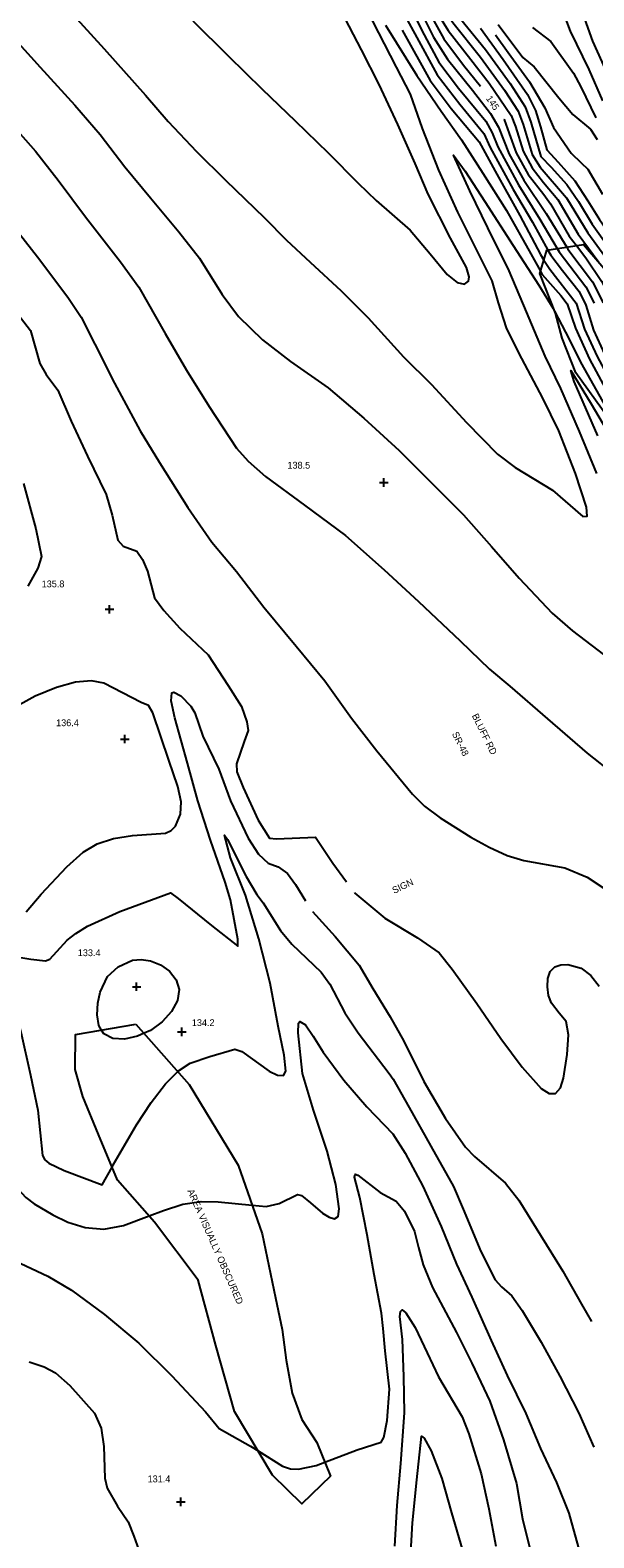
# Model space of a CAD drawing. Extents: x 1475150 to 2003689, y 770235 to 1112803.
# Drawn here: x 2002493.7 to 2002659.6, y 770837.9 to 771281.4 of the extents above; entities that cross this region are included whole.
import ezdxf

# ---------------------------------------------------------------- set-up
doc = ezdxf.new("R2010")
doc.units = 0
for name, color, linetype in [('RD_DTM_Major1', 7, 'Continuous'), ('RD_DTM_Major1_Lbl', 7, 'Continuous'), ('RD_DTM_Major2', 7, 'Continuous'), ('RD_DTM_Minor1', 7, 'Continuous'), ('RD_DTM_Minor2', 7, 'Continuous'), ('RD_DTM_Obscure', 7, 'Continuous'), ('RD_DTM_Spot_Elev', 7, 'Continuous'), ('RD_TX_Misc1', 7, 'Continuous')]:
    doc.layers.add(name, color=color, linetype=linetype)

msp = doc.modelspace()

# ---------------------------------------------------------------- linework, layer by layer
at = {"layer": 'RD_DTM_Major1'}
for points in [[(2002572.22, 771348.32), (2002573.98, 771345.49), (2002577.35, 771341.32), (2002584.21, 771333.66), (2002588.04, 771328.3), (2002594.85, 771316.81), (2002600.6, 771307.87), (2002604.96, 771301.61), (2002605.97, 771297.81), (2002610.02, 771288.75), (2002615.43, 771278.87), (2002621.3, 771271.13), (2002626.24, 771264.94)], [(2002505.43, 771287.05), (2002515.49, 771275.9), (2002527.71, 771262.34), (2002534.33, 771254.58), (2002542.66, 771245.73), (2002551.18, 771237.34), (2002562.67, 771226.24), (2002569.19, 771219.64), (2002576.1, 771213.22), (2002585.28, 771204.7), (2002593.19, 771196.77), (2002603.59, 771185.34), (2002611.84, 771177.15), (2002622.17, 771165.97), (2002631.32, 771156.68), (2002636.45, 771152.77), (2002647.44, 771146.13), (2002656.34, 771138.4), (2002657.65, 771138.48), (2002657.48, 771141.15), (2002654.26, 771151.06), (2002649.3, 771163.55), (2002644.63, 771173.15), (2002637.52, 771186.52), (2002633.96, 771193.89), (2002631.57, 771201.26), (2002629.69, 771207.66), (2002625.75, 771215.49), (2002619.56, 771227.86), (2002614.03, 771240.2), (2002609.17, 771252.46), (2002605.63, 771262.63), (2002601.57, 771270.55), (2002592.83, 771287.51)], [(2002598.29, 771282.91), (2002607.56, 771268.03), (2002614.7, 771257.57), (2002620.71, 771249.16), (2002627, 771239.37), (2002633.93, 771228.36), (2002641.08, 771215.63), (2002643.95, 771210.51)], [(2002630.69, 771280.05), (2002634.41, 771274.84), (2002640.69, 771266.18), (2002645.22, 771258.55), (2002647.73, 771252.77), (2002652.97, 771245.24), (2002655.86, 771242.37), (2002657.82, 771240.5), (2002662.21, 771233.14)], [(2002633.18, 771255.15), (2002633.23, 771255.09), (2002634.67, 771250.97), (2002636.76, 771245.36), (2002640.31, 771239), (2002644.89, 771233.03), (2002646.86, 771230.34), (2002652.4, 771220.85), (2002654.53, 771218.04)], [(2002491.78, 771148.03), (2002495.42, 771134.7), (2002497.04, 771126.58), (2002496.03, 771123.14), (2002493.09, 771117.87)], [(2002486.81, 771009.34), (2002493.88, 771008.19), (2002498.27, 771007.64), (2002499.54, 771008.14), (2002501.56, 771010.38), (2002504.63, 771013.75), (2002507.15, 771015.74), (2002510.62, 771017.88), (2002520.12, 771022.23), (2002535.04, 771027.72), (2002537.29, 771026.02), (2002547.09, 771018.1), (2002554.87, 771012), (2002554.88, 771014.09), (2002552.73, 771025.64), (2002551.09, 771030.78), (2002546.76, 771043.18), (2002543.12, 771054.78), (2002540.05, 771065.8), (2002536.34, 771079.12), (2002535.23, 771084.16), (2002535.4, 771086.53), (2002536.04, 771086.74), (2002538.07, 771085.6), (2002541.05, 771082.59), (2002542.18, 771080.66), (2002544.5, 771073.8), (2002549.22, 771064.09), (2002552.66, 771054.73), (2002557.89, 771043.77), (2002560.94, 771039.09), (2002563.77, 771036.36), (2002566.68, 771035.33), (2002569.47, 771033.4), (2002571.84, 771030.16), (2002574.72, 771025.34)], [(2002576.86, 771022.2), (2002583.53, 771014.84), (2002590.51, 771006.44), (2002594.56, 770999.56), (2002599.68, 770991.22), (2002603.74, 770984.01), (2002609.55, 770972.21), (2002615.96, 770961.34), (2002621.83, 770952.86), (2002624.5, 770950.16), (2002633.66, 770942.29), (2002637.54, 770937.31), (2002643.96, 770927), (2002650.46, 770916.36), (2002655.97, 770906.66), (2002658.93, 770901.54)], [(2002605.7, 770831.98), (2002606.26, 770842.36), (2002607.56, 770855.02), (2002608.89, 770867.88), (2002609.67, 770867.25), (2002611.71, 770863.59), (2002614.92, 770855.4), (2002617.72, 770845.32), (2002620.86, 770834.63)]]:
    msp.add_lwpolyline(points, dxfattribs=at)
at = {"layer": 'RD_DTM_Major2'}
for points in [[(2002654.53, 771218.04), (2002657.25, 771214.47), (2002661.88, 771207.57), (2002665.07, 771201.19), (2002668.33, 771190.58), (2002672.37, 771182.9), (2002679.57, 771170.99), (2002683.76, 771163.78), (2002685.58, 771159.2), (2002690.3, 771152.5), (2002695.01, 771145.03), (2002698.68, 771139.17), (2002704.48, 771129.17), (2002711.31, 771116.67), (2002715.88, 771105.6), (2002718.71, 771098.65), (2002724.7, 771088.03), (2002731.15, 771076.17), (2002737.25, 771064.57), (2002741.23, 771052.36), (2002742.65, 771048.71), (2002746.13, 771042.89), (2002752.29, 771034.5), (2002755.03, 771032.17)], [(2002643.95, 771210.51), (2002644.46, 771209.59), (2002649.94, 771203.39), (2002651.75, 771200.95), (2002654.18, 771193.76), (2002658.38, 771184.61), (2002665.58, 771171.25), (2002674.36, 771155.85), (2002675.88, 771153.09)]]:
    msp.add_lwpolyline(points, dxfattribs=at)
at = {"layer": 'RD_DTM_Minor1'}
for points in [[(2002563.7, 771348.73), (2002564.68, 771347.23), (2002571.43, 771336.99), (2002577.44, 771328.72), (2002582, 771323.14), (2002588.01, 771313.39), (2002593.54, 771304.04), (2002599.77, 771293.47), (2002607.5, 771279.21), (2002613.52, 771268.25), (2002620.16, 771259.63), (2002627.23, 771250.99), (2002629.12, 771246.88), (2002635.91, 771234.5), (2002641.58, 771224.89), (2002646.13, 771216.72)], [(2002573.94, 771349.72), (2002574.3, 771348.98), (2002576.95, 771345.69), (2002584.23, 771337.11), (2002589.63, 771329.59), (2002596.09, 771318.77), (2002601.43, 771310.98), (2002606.98, 771303.89), (2002607.87, 771300.41), (2002609.33, 771295.5), (2002613.46, 771286.7), (2002616.75, 771281.28), (2002623.47, 771272.76), (2002628.82, 771265.82), (2002635.27, 771256.35), (2002636.53, 771253.08), (2002638.81, 771245.8), (2002641.47, 771240.88), (2002644.82, 771236.58), (2002648.99, 771231.6), (2002655.05, 771221.37), (2002661.06, 771213.22)], [(2002575.89, 771351.44), (2002576.58, 771350.03), (2002582.73, 771342.53), (2002589.49, 771333.59), (2002595.87, 771323.12), (2002600.5, 771316.2), (2002609.15, 771305.7), (2002610.34, 771301.7), (2002611.17, 771297.43), (2002612.62, 771293.24), (2002615, 771288.4), (2002618.08, 771283.68), (2002626.3, 771273.43), (2002633.38, 771263.74), (2002637.32, 771257.61), (2002638.82, 771253.7), (2002641.43, 771244.88), (2002643.81, 771241.14), (2002651.57, 771232.08), (2002657.87, 771221.85), (2002663.92, 771213.45), (2002669.14, 771204.3), (2002669.57, 771203.14)], [(2002567.49, 771347.27), (2002569.48, 771344.18), (2002575.21, 771336.07), (2002579.71, 771330.85), (2002584.76, 771325.85), (2002590.51, 771316.05), (2002597.59, 771303.89), (2002602.2, 771295.17), (2002608.96, 771281.32), (2002614.05, 771271.97), (2002619.79, 771264.34), (2002627.82, 771254.6), (2002629.66, 771251.23), (2002631.36, 771247.06), (2002637.45, 771235.91), (2002643.75, 771225.87), (2002648.85, 771217.15)], [(2002570.06, 771347.46), (2002571.07, 771345.82), (2002576.99, 771337.75), (2002585.68, 771328.2), (2002591.13, 771319.05), (2002598.23, 771307.18), (2002602.8, 771299.41), (2002606.11, 771292), (2002612.42, 771279.4), (2002616.56, 771272.89), (2002623.91, 771263.77), (2002629.21, 771256.89), (2002631.6, 771252.88), (2002634.71, 771244.93), (2002638.99, 771237.33), (2002645.61, 771227.51), (2002651.63, 771217.59)], [(2002541.63, 771284.14), (2002551.97, 771273.86), (2002562.01, 771264.07), (2002571.72, 771254.71), (2002581.44, 771245.32), (2002590.25, 771236.41), (2002595.57, 771231.34), (2002605.59, 771222.62), (2002611.5, 771215.6), (2002616.49, 771209.56), (2002619.39, 771207.15), (2002621.52, 771206.7), (2002622.71, 771207.56), (2002622.96, 771208.84), (2002622.11, 771211.57), (2002617.44, 771220.27), (2002610.9, 771233.19), (2002607.08, 771242.19), (2002601.95, 771253.65), (2002596.41, 771265.41), (2002591.23, 771275.64), (2002585.28, 771287.14)], [(2002655.93, 771287.52), (2002659.19, 771278.16), (2002664.19, 771267.1)], [(2002620.4, 771284.79), (2002627.7, 771275.75), (2002634.98, 771265.73), (2002639.37, 771258.87), (2002641.12, 771254.32), (2002644.06, 771244.25), (2002647.11, 771241.07), (2002651.72, 771236.05), (2002655.09, 771230.98), (2002659.16, 771224.32), (2002665.72, 771215.11), (2002670.85, 771206.26), (2002673.09, 771201.25), (2002674.04, 771197.67)], [(2002631.5, 771283.04), (2002638.71, 771273.42), (2002642.07, 771270.67), (2002649.36, 771261.5), (2002653.44, 771256.63), (2002658.67, 771252.3), (2002660.56, 771249.21)], [(2002641.59, 771282.18), (2002647, 771278.05), (2002653.63, 771268.72), (2002655.78, 771264.73), (2002660.23, 771255.65)], [(2002651.31, 771284.77), (2002652.7, 771281.08), (2002658.14, 771269.86), (2002662.13, 771260.66)], [(2002489.33, 771278.64), (2002496.7, 771270.53), (2002506.85, 771259.31), (2002514.29, 771250.77), (2002521.57, 771241.25), (2002529.11, 771232.07), (2002537.51, 771222.13), (2002543.59, 771214.39), (2002550.22, 771203.66), (2002555.04, 771197.19), (2002562.15, 771190.29), (2002570.36, 771184), (2002581.41, 771176.21), (2002591.94, 771167.32), (2002602.37, 771157.75), (2002611.1, 771149.07), (2002621.22, 771138.87), (2002629.53, 771129.56), (2002637.62, 771120.26), (2002647.4, 771109.9), (2002653.31, 771104.72), (2002664.56, 771096.17)], [(2002603.19, 771281.43), (2002611.49, 771266.63), (2002617.64, 771258.36), (2002625.83, 771248.6), (2002630.59, 771239.9), (2002637.88, 771226.89), (2002643.88, 771215.46), (2002644.94, 771213.79)], [(2002626.23, 771282.02), (2002632.93, 771272.81), (2002640.12, 771262.5), (2002642.5, 771257.82), (2002643.96, 771252.97), (2002645.8, 771246.23), (2002649.11, 771242.59), (2002654, 771237.12), (2002657.83, 771231.18), (2002661.26, 771225.68), (2002667.52, 771216.78), (2002673.25, 771206.89), (2002676.25, 771200.55), (2002677.87, 771196.72), (2002683.73, 771187.33), (2002686.54, 771181.81), (2002688.22, 771177.12)], [(2002487.12, 771255), (2002495.3, 771245.85), (2002501.99, 771237.26), (2002510, 771226.51), (2002520.31, 771213.23), (2002525.69, 771205.81), (2002533.48, 771192.21), (2002539.77, 771181.38), (2002546.41, 771170.75), (2002554.44, 771158.5), (2002557.86, 771154.65), (2002562.96, 771150.12), (2002574.5, 771141.71), (2002586.58, 771132.76), (2002597.92, 771122.64), (2002607.98, 771113.41), (2002620.3, 771101.82), (2002628.91, 771093.47), (2002634.9, 771088.45), (2002645.95, 771078.84), (2002657.65, 771068.77), (2002665.57, 771062.52)], [(2002660.51, 771151.02), (2002655.39, 771163.4), (2002649.93, 771176.06), (2002645.33, 771185.53), (2002639.8, 771198.61), (2002634.68, 771210.58), (2002628.46, 771223.28), (2002623.09, 771234.12), (2002618.34, 771244.69), (2002621.75, 771239.9), (2002627.53, 771231.04), (2002635.92, 771218.07), (2002643.4, 771206.44), (2002647.66, 771199.57), (2002648.09, 771198.74)], [(2002487.08, 771226.04), (2002495.93, 771214.74), (2002504.79, 771202.89), (2002508.72, 771196.95), (2002512.78, 771189.04), (2002518.54, 771177.6), (2002526.06, 771163.61), (2002531.82, 771154.24), (2002540.11, 771141.04), (2002547.21, 771130.78), (2002554.44, 771122.14), (2002562.46, 771111.67), (2002571.99, 771100.27), (2002580.46, 771090.03), (2002588.32, 771079.06), (2002595.77, 771069.43), (2002606.28, 771056.66), (2002609.77, 771053.19), (2002614.39, 771049.77), (2002623.42, 771044.01), (2002628.81, 771041.07), (2002634.13, 771038.7), (2002639.01, 771037.19), (2002651.04, 771035), (2002657.63, 771032.29), (2002667.5, 771025.85)], [(2002489.17, 771199.09), (2002493.82, 771193.05), (2002496.54, 771183.41), (2002498.48, 771180.13), (2002501.88, 771175.52), (2002505.79, 771166.36), (2002510.63, 771156.08), (2002516.12, 771144.82), (2002517.84, 771138.71), (2002519.5, 771131.39), (2002521.11, 771129.6), (2002525.12, 771128.14), (2002526.83, 771125.74), (2002528.24, 771122.33), (2002530.37, 771114.44), (2002533.11, 771110.71), (2002537.78, 771105.48), (2002546.1, 771097.65), (2002552.02, 771088.64), (2002555.94, 771082.47), (2002557.54, 771077.98), (2002557.93, 771075.41), (2002556.71, 771072.21), (2002554.43, 771065.63), (2002554.55, 771063.29), (2002556.45, 771058.64), (2002560.88, 771049.05), (2002564.12, 771043.74), (2002566.26, 771043.58), (2002577.7, 771044.06), (2002582.84, 771036.36), (2002586.86, 771030.89)], [(2002660.82, 771162.11), (2002653.8, 771178.06), (2002652.83, 771181.31), (2002658.86, 771171.46), (2002666.86, 771157.92)], [(2002492.57, 771022.13), (2002496.94, 771027.3), (2002504.5, 771035.34), (2002509.32, 771039.62), (2002513.46, 771042.12), (2002518.24, 771043.63), (2002523.83, 771044.53), (2002533.57, 771045.25), (2002535.25, 771045.99), (2002536.53, 771047.27), (2002537.99, 771050.84), (2002538.21, 771054.41), (2002537.15, 771058.95), (2002534.56, 771066.72), (2002529.83, 771080.58), (2002528.55, 771082.82), (2002526.38, 771083.67), (2002515.38, 771089.32), (2002511.82, 771090.03), (2002507.1, 771089.68), (2002501.46, 771088.11), (2002495.2, 771085.52), (2002487.08, 771081)], [(2002537.15, 770975.08), (2002537.37, 770975.3), (2002540.82, 770977.54), (2002546.56, 770979.57), (2002553.94, 770981.73), (2002556.06, 770981), (2002564.07, 770975.18), (2002566.51, 770974.05), (2002568.28, 770973.94), (2002569.02, 770975.18), (2002568.44, 770979.97), (2002566.7, 770988.46), (2002564.37, 771001.15), (2002561.05, 771014.14), (2002557.12, 771026.94), (2002552.73, 771037.96), (2002550.89, 771044.65), (2002551.78, 771043.34), (2002557.32, 771032.52), (2002560.42, 771027.18), (2002562.26, 771024.69), (2002567.43, 771016.62), (2002570.79, 771012.53), (2002579.37, 771004.32), (2002581.94, 771000.79), (2002586.35, 770992.36), (2002590.29, 770986.48), (2002599.42, 770974.52), (2002600.53, 770972.83), (2002605.27, 770964.49), (2002611.69, 770953.13), (2002618.37, 770941.31), (2002621.16, 770934.6), (2002626.33, 770922.13), (2002630.55, 770913.86), (2002632.44, 770911.82), (2002635.51, 770909.18), (2002638.52, 770904.8), (2002644.1, 770895.52), (2002649.62, 770885.47), (2002655.16, 770874.66), (2002659.66, 770864.61)], [(2002589.14, 771027.79), (2002589.3, 771027.56), (2002598.14, 771020.25), (2002607.74, 771014.39), (2002614.09, 771010.02), (2002617.95, 771005.25), (2002625.19, 770995.1), (2002632.27, 770984.86), (2002638.5, 770976.35), (2002644.16, 770970.12), (2002646.49, 770968.64), (2002648.38, 770968.65), (2002649.77, 770970.29), (2002650.74, 770973.14), (2002651.8, 770980.15), (2002652.17, 770985.94), (2002651.47, 770989.84), (2002649.41, 770992.32), (2002647.13, 770995.26), (2002646.33, 770997.48), (2002645.94, 771000), (2002646.05, 771002.47), (2002646.77, 771004.52), (2002648.13, 771005.87), (2002649.95, 771006.54), (2002651.99, 771006.63), (2002655.85, 771005.47), (2002658.71, 771003.33), (2002661.15, 771000.23)], [(2002514.75, 770987.31), (2002513.96, 770988.62), (2002513.46, 770991.81), (2002513.68, 770995.26), (2002514.36, 770998.47), (2002516.47, 771003.07), (2002519.59, 771005.94), (2002523.85, 771007.82), (2002526.38, 771008.1), (2002529.14, 771007.71), (2002532.04, 771006.52), (2002534.71, 771004.61), (2002536.72, 771002.12), (2002537.63, 770999.19), (2002537.12, 770995.97), (2002535.36, 770992.72), (2002532.62, 770989.71), (2002529.18, 770987.22), (2002527.24, 770986.35)], [(2002456.63, 770992.09), (2002467.5, 770996.08), (2002480.82, 771000.79), (2002482.72, 771000.63), (2002484.61, 770999.93), (2002486.39, 770998.6), (2002487.95, 770996.56), (2002489.2, 770993.76), (2002491.03, 770986.82), (2002493.79, 770974.07), (2002496.02, 770963.78), (2002497.38, 770950.37), (2002498.08, 770949.09), (2002499.26, 770948.11), (2002503.73, 770946.02), (2002514.91, 770941.81), (2002517.82, 770946.96)], [(2002559.08, 770935.8), (2002563.16, 770935.39), (2002567.03, 770936.34), (2002572.45, 770938.94), (2002573.63, 770938.6), (2002576.27, 770936.51), (2002579.78, 770933.46), (2002581.69, 770932.23), (2002583.33, 770931.76), (2002584.41, 770932.5), (2002584.72, 770934.74), (2002583.7, 770941.86), (2002581.18, 770951.69), (2002577.13, 770963.76), (2002573.86, 770974.51), (2002572.59, 770986.49), (2002572.66, 770989.37), (2002573.14, 770989.78), (2002574.72, 770988.86), (2002577.06, 770985.54), (2002580, 770980.76), (2002586.03, 770972.61), (2002592.82, 770964.72), (2002600.48, 770956.81), (2002604.06, 770951.07), (2002609.25, 770941.4), (2002614.66, 770929.55), (2002619.24, 770918.44), (2002623.73, 770908.74), (2002629.4, 770895.95), (2002634.1, 770885.71), (2002639.62, 770874.54), (2002643.96, 770864.27), (2002648.59, 770854.25), (2002652.28, 770845.24), (2002655.46, 770833.5)], [(2002449.77, 770982.48), (2002459.34, 770987.64), (2002465.01, 770989.08), (2002467.43, 770988.98), (2002469.28, 770988.14), (2002470.63, 770986.66), (2002472.46, 770982.41), (2002475.72, 770970.69), (2002479.97, 770956.5), (2002481.82, 770950.52), (2002484.83, 770946.24), (2002492.41, 770938.02), (2002494.89, 770936.19), (2002500.41, 770932.92), (2002504.77, 770930.82), (2002509.88, 770929.21), (2002515.45, 770928.74), (2002521.24, 770929.81), (2002528.73, 770932.65)], [(2002438.46, 770950.79), (2002437.24, 770945.49), (2002437.02, 770937.15), (2002437.39, 770936.36), (2002439.36, 770935.27), (2002447.11, 770933.43), (2002450.77, 770932.81), (2002454.21, 770931.71), (2002458.28, 770931.85), (2002463.62, 770932.38), (2002466.03, 770932.19), (2002468.01, 770931.44), (2002475.22, 770926.39), (2002484.44, 770921.7), (2002498.9, 770914.88), (2002505.92, 770910.8), (2002515.6, 770903.66), (2002525.72, 770895.19), (2002535.45, 770885.57), (2002545.38, 770875.06), (2002549.34, 770870.1), (2002558.62, 770864.92), (2002560.82, 770863.55)], [(2002580.43, 770860.22), (2002590.01, 770863.84), (2002597.03, 770866.12), (2002597.8, 770867.44), (2002598.83, 770872.43), (2002599.52, 770881.64), (2002598.22, 770892.95), (2002597.61, 770899.5), (2002597.1, 770904), (2002594.99, 770915.38), (2002592.95, 770927.03), (2002590.71, 770938.01), (2002589.19, 770944.04), (2002589.36, 770944.93), (2002590.18, 770944.67), (2002596.74, 770939.56), (2002601.47, 770937), (2002603.92, 770933.99), (2002606.82, 770928.09), (2002608.02, 770923.35), (2002609.37, 770918.27), (2002612.15, 770911.6), (2002619.25, 770898.39), (2002623.72, 770889.31), (2002629.02, 770878.11), (2002633.06, 770866.82), (2002636.9, 770853.96), (2002638.66, 770843.59), (2002641.15, 770833.27)], [(2002601.09, 770835.53), (2002601.72, 770847.48), (2002602.82, 770859.79), (2002603.88, 770874.7), (2002603.7, 770885.41), (2002603.28, 770896.26), (2002602.52, 770903.1), (2002602.68, 770904.55), (2002603.23, 770905.03), (2002604.25, 770904.18), (2002607.05, 770899.81), (2002610.53, 770892.38), (2002613.88, 770885.33), (2002620.85, 770873.55), (2002622.86, 770868.58), (2002626.51, 770856.74), (2002628.75, 770846.52), (2002630.82, 770835.53)], [(2002493.47, 770889.68), (2002497.86, 770888.21), (2002501.18, 770886.5), (2002505.41, 770882.8), (2002512.71, 770874.61), (2002514.58, 770870.23), (2002515.43, 770864.79), (2002515.74, 770855.52), (2002516.43, 770852.56), (2002519.4, 770847.29), (2002522.58, 770842.68), (2002524.2, 770838.4), (2002525.73, 770834.31)]]:
    msp.add_lwpolyline(points, dxfattribs=at)
at = {"layer": 'RD_DTM_Minor2'}
for points in [[(2002646.13, 771216.72), (2002646.94, 771215.25), (2002650.37, 771210.72), (2002655.29, 771204.54), (2002657.25, 771200.5), (2002659.56, 771193.17), (2002662.76, 771186.16)], [(2002648.85, 771217.15), (2002649.41, 771216.19), (2002657.25, 771205.96), (2002659.72, 771201.15)], [(2002651.63, 771217.59), (2002651.98, 771217.02), (2002659.2, 771207.38), (2002662.4, 771201.17)], [(2002644.94, 771213.79), (2002646.68, 771211.07), (2002654.38, 771201.11), (2002656.87, 771193.46), (2002660.57, 771185.39), (2002666.94, 771173.58), (2002675.07, 771159.41), (2002681.48, 771147.8), (2002685.24, 771141.72), (2002690.25, 771133.09), (2002697.53, 771120.49), (2002705.83, 771105.64), (2002710.2, 771095.31), (2002714.36, 771087.8), (2002719.59, 771077.94), (2002727.4, 771063.25), (2002729.65, 771058.92), (2002733.04, 771047.46), (2002734.7, 771044.17), (2002738.92, 771038.02), (2002745.57, 771029.85), (2002751.93, 771023.76), (2002752.19, 771023.44)], [(2002648.09, 771198.74), (2002652.4, 771190.53), (2002655.73, 771183.76), (2002662.31, 771172.05), (2002666.86, 771163.98)], [(2002527.24, 770986.35), (2002525.34, 770985.5), (2002521.49, 770984.67), (2002518.05, 770984.86), (2002515.44, 770986.17), (2002514.75, 770987.31)], [(2002517.82, 770946.96), (2002518.2, 770947.62), (2002525.06, 770959.43), (2002529.3, 770965.98), (2002533.52, 770971.53), (2002537.15, 770975.08)], [(2002528.73, 770932.65), (2002532.94, 770934.25), (2002538.62, 770936.1), (2002544.02, 770936.88), (2002549.03, 770936.79), (2002559.08, 770935.8)], [(2002560.82, 770863.55), (2002568.04, 770859.01), (2002570.31, 770858.29), (2002572.67, 770858.14), (2002577.86, 770859.24), (2002580.43, 770860.22)]]:
    msp.add_lwpolyline(points, dxfattribs=at)
at = {"layer": 'RD_DTM_Obscure'}
for points in [[(2002663.69, 771167.67), (2002654.36, 771180.62), (2002650.28, 771190.85), (2002648.31, 771198.19), (2002643.74, 771209.82), (2002645.81, 771216.67), (2002656.63, 771218.38), (2002666.82, 771206.52)], [(2002524.87, 770989.04), (2002540.5, 770971.28), (2002554.99, 770947.61), (2002562, 770927.36), (2002565.97, 770908.5), (2002567.92, 770899.23), (2002569.1, 770890.2), (2002570.82, 770880.54), (2002573.67, 770872.77), (2002578.06, 770865.95), (2002582.13, 770856.11), (2002573.65, 770847.91), (2002565.06, 770856.42), (2002553.91, 770875.14), (2002548.4, 770894.52), (2002543.18, 770913.77), (2002530.34, 770930.84), (2002519.39, 770943.15), (2002513.84, 770956.63), (2002509.19, 770967.78), (2002506.94, 770975.7), (2002507.03, 770986), (2002524.87, 770989.04)]]:
    msp.add_lwpolyline(points, dxfattribs=at)
at = {"layer": 'RD_DTM_Spot_Elev'}
for p, q in [((2002597.83, 771147.13), (2002597.83, 771149.63)), ((2002596.58, 771148.38), (2002599.08, 771148.38)), ((2002515.81, 771111.06), (2002518.31, 771111.06)), ((2002517.06, 771109.81), (2002517.06, 771112.31)), ((2002521.61, 771071.65), (2002521.61, 771074.15)), ((2002520.36, 771072.9), (2002522.86, 771072.9)), ((2002523.8, 771000.05), (2002526.3, 771000.05)), ((2002525.05, 770998.8), (2002525.05, 771001.3)), ((2002537.11, 770986.78), (2002539.61, 770986.78)), ((2002538.36, 770985.53), (2002538.36, 770988.03)), ((2002536.84, 770848.52), (2002539.34, 770848.52)), ((2002538.09, 770847.27), (2002538.09, 770849.77))]:
    msp.add_line(p, q, dxfattribs=at)

# ---------------------------------------------------------------- texts
at = {"layer": 'RD_DTM_Major1_Lbl'}
msp.add_text('145', height=2, rotation=304.2954, dxfattribs=at).set_placement((2002627.78, 771261.31))
at = {"layer": 'RD_DTM_Spot_Elev'}
for s, p in [('138.5', (2002569.45, 771152.44)), ('135.8', (2002497.11, 771117.54)), ('136.4', (2002501.37, 771076.69)), ('133.4', (2002507.75, 771009.05)), ('134.2', (2002541.31, 770988.49)), ('131.4', (2002528.29, 770854.29))]:
    msp.add_text(s, height=2, dxfattribs=at).set_placement(p)
at = {"layer": 'RD_TX_Misc1'}
for s, rotation, p in [('BLUFF RD', 296.151, (2002623.67, 771079.78)), ('SR-48', 296.151, (2002617.8, 771074.47)), ('SIGN', 25.641, (2002600.86, 771027.34)), ('AREA VISUALLY OBSCURED', 293.7495, (2002539.95, 770940.02))]:
    msp.add_text(s, height=2, rotation=rotation, dxfattribs=at).set_placement(p)

doc.saveas('drawing.dxf')
